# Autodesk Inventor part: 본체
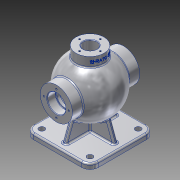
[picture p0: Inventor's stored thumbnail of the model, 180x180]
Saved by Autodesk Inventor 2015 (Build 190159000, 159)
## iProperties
Created: 2025-08
Part Number: 본체
Material: 알루미늄 6061
Document SubType Name: Modeling
Designer: USER
Density: 2.7 g/cm^3
Appearance: 알루미늄 - 평지
Mass: 1478.47 g
Surface Area: 1180.43 cm^2
Volume: 547.582 cm^3
Author: USER
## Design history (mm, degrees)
sketch "스케치1"
  geometry: L1 (-62.5, 62.5)-(62.5, 62.5); L2 (62.5, 62.5)-(62.5, -62.5); L3 (62.5, -62.5)-(-62.5, -62.5); L4 (-62.5, -62.5)-(-62.5, 62.5); L5 (-62.5, 62.5)-(62.5, -62.5); L6 (62.5, 62.5)-(-62.5, -62.5); 1 further point
  constraints: 12 end point, 2 midpoint, 2 parallel, 1 horizontal, 1 perpendicular
  dimensions: "d0" = 125 distance of L2.end L3.end; "d1" = 125 distance of L1.end L2.end
extrude "돌출1" new body sketch "스케치1" distance "d2" = 10; taper "d3" = 0 deg
sketch "스케치2"
  geometry: L1 (62.5, 10)-(62.5, 0) reference; L2 (62.5, 0)-(-62.5, 0) reference; L3 (-62.5, 0)-(-62.5, 10) reference; L4 (-62.5, 10)-(62.5, 10) reference; L5 (0, 139)-(0, 31); A1 r 54 centre (0, 85) between (0, 139) and (0, 31); 3 further points
  constraints: 2 end point, 2 midpoint, 2 point on circle, 1 centre point, 1 coincident, 1 vertical, 1 vertical alignment
  dimensions: "d4" = 108 diameter of A1; "d5" = 85 distance from line of A1.centre L2
revolve "회전1" sketch "스케치2" stored, may be unused: angle "d6" = 90 deg
sketch "스케치5"
  geometry: L1 (-4, -50.5)-(4, -50.5); L2 (4, -50.5)-(4, 50.5); L3 (4, 50.5)-(-4, 50.5); L4 (-4, 50.5)-(-4, -50.5); L5 (-4, -50.5)-(4, 50.5); L6 (4, -50.5)-(-4, 50.5); L7 (-50.5, -4)-(50.5, -4); L8 (50.5, -4)-(50.5, 4); L9 (50.5, 4)-(-50.5, 4); L10 (-50.5, 4)-(-50.5, -4); L11 (-50.5, -4)-(50.5, 4); L12 (50.5, -4)-(-50.5, 4); L13 (-62.5, -62.5)-(-62.5, 62.5) reference; L14 (-62.5, 62.5)-(62.5, 62.5) reference; 1 further point
  constraints: 24 end point, 4 midpoint, 4 parallel, 2 horizontal, 2 perpendicular
  dimensions: "d15" = 12 distance between parallel lines of L10 L13; "d16" = 12 distance between parallel lines of L3 L14; "d17" = 8 distance between parallel lines of L9 L7; "d18" = 8 distance between parallel lines of L4 L2
extrude "돌출4" join sketch "스케치5" distance "d19" = 85; taper "d20" = 0 deg
feature "면 기울기1" dims angle "d21" = 20 deg
node "작업 평면1"
sketch "스케치6"
  geometry: L1 (-25.074, 11.167)-(16.405, 11.167); L2 (16.405, 11.167)-(16.405, 5.163); L3 (16.405, 5.163)-(-25.074, 5.163); L4 (-25.074, 5.163)-(-25.074, 11.167); C1 r 27 at (0, 0); 1 further point
  constraints: 1 centre point, 1 coincident, 2 other
  dimensions: "d23" = 54 diameter of C1
extrude "돌출5" join sketch "스케치6" stored distance "d24" = 85; taper "d25" = 0 deg
node "작업 평면2"
sketch "스케치7"
  geometry: C1 r 31 at (0, 85); 1 further point
  constraints: 1 centre point, 1 vertical alignment
  dimensions: "d27" = 62 diameter of C1; "d28" = 85 distance of C1.centre point (0, 0)
extrude "돌출6" join sketch "스케치7" distance "d29" = 130; taper "d30" = 0 deg
hole "구멍1" diameter "d39" = 30; stored, may be unused: countersink angle "d43" = 90 deg, drill point angle "d45" = 0 deg; dims "d37" = 10, "d38" = 10, "d40" = 6, "d41" = 35, "d42" = 16, "d44" = 8
hole "구멍2" diameter "d48" = 26; stored, may be unused: countersink angle "d52" = 90 deg, drill point angle "d54" = 0 deg; dims "d46" = 10, "d47" = 10, "d49" = 6, "d50" = 35, "d51" = 16, "d53" = 100
sketch "스케치10"
  geometry: L1 (0, 0)-(0, 24); 1 further point
  constraints: 2 end point, 1 vertical
  dimensions: "d55" = 24 distance of L1.start L1.end
hole "구멍3" sketch "스케치10" at (0, 24) diameter "d56" = 3.242; stored, may be unused: countersink angle "d60" = 90 deg, drill point angle "d62" = 118 deg; dims "d57" = 12, "d58" = 35, "d59" = 16, "d61" = 15
sketch "스케치11"
  geometry: L1 (0, 0)-(0, 20)
  constraints: 2 end point, 1 vertical
  dimensions: "d66" = 20 distance of L1.start L1.end
hole "구멍4" sketch "스케치11" at (0, 20) diameter "d67" = 3.242; stored, may be unused: countersink angle "d71" = 90 deg, drill point angle "d73" = 118 deg; dims "d68" = 9, "d69" = 35, "d70" = 16, "d72" = 11
fillet "모깎기1" dims "d78" = 16
hole "구멍5" diameter "d81" = 11; stored, may be unused: countersink angle "d85" = 90 deg, drill point angle "d87" = 0 deg; dims "d79" = 10, "d80" = 10, "d82" = 203.2, "d83" = 35, "d84" = 16, "d86" = 11
hole "구멍6" diameter "d90" = 11; stored, may be unused: countersink angle "d94" = 90 deg, drill point angle "d96" = 0 deg; dims "d88" = 10, "d89" = 10, "d91" = 203.2, "d92" = 35, "d93" = 16, "d95" = 11
hole "구멍7" diameter "d99" = 11; stored, may be unused: countersink angle "d103" = 90 deg, drill point angle "d105" = 0 deg; dims "d97" = 10, "d98" = 10, "d100" = 203.2, "d101" = 35, "d102" = 16, "d104" = 11
hole "구멍8" diameter "d108" = 11; stored, may be unused: countersink angle "d112" = 90 deg, drill point angle "d114" = 0 deg; dims "d106" = 10, "d107" = 10, "d109" = 203.2, "d110" = 35, "d111" = 16, "d113" = 11
sketch "스케치13"
  geometry: L1 (-13, 150)-(13, 150) reference; 3 further points
  constraints: 1 midpoint, 1 vertical alignment, 1 other
  dimensions: "d115" = 9 distance from line of point (0, 141) L1
feature "엠보싱1" sketch "스케치13" dims "d0" = 125, "d1" = 125, "d16" = 12, "d18" = 8, "d116" = 0.5, "d117" = 0
chamfer "모따기1" distance "d118" = 1; stored, may be unused: second distance "d119" = 2, angle "d120" = 45 deg
fillet "모깎기2" dims "d121" = 0.6
fillet "모깎기3" dims "d122" = 3
fillet "모깎기4" dims "d123" = 3
sketch "스케치14"
  geometry: L1 (50, 110.621)-(49.026, 109) reference; L2 (49.026, 109)-(50, 107.379) reference; L3 (50, 107.379)-(65, 107.379) reference; L4 (65, 107.379)-(65, 103.5) reference; L5 (65, 103.5)-(64, 102.5) reference; L6 (64, 102.5)-(49.6, 102.5) reference; L7 (49, 101.9)-(49, 100) reference; L8 (49, 100)-(13, 100) reference; L9 (13, 100)-(13, 149) reference; L10 (13, 149)-(14, 150) reference; L11 (14, 150)-(18.379, 150) reference; L12 (18.379, 150)-(18.379, 139) reference; L13 (18.379, 139)-(20, 138.026) reference; L14 (20, 138.026)-(21.621, 139) reference; L15 (21.621, 139)-(21.621, 150) reference; L16 (21.621, 150)-(27, 150) reference; L17 (27, 150)-(27, 133.466) reference; L18 (45.749, 116)-(65, 116) reference; L19 (65, 116)-(65, 110.621) reference; L20 (65, 110.621)-(50, 110.621) reference; L21 (-49.026, 109)-(-50, 110.621) reference; L22 (-50, 110.621)-(-65, 110.621) reference; L23 (-65, 110.621)-(-65, 116) reference; L24 (-65, 116)-(-45.749, 116) reference; L25 (-27, 133.466)-(-27, 150) reference; L26 (-27, 150)-(-21.621, 150) reference; L27 (-21.621, 150)-(-21.621, 139) reference; L28 (-21.621, 139)-(-20, 138.026) reference; L29 (-20, 138.026)-(-18.379, 139) reference; L30 (-18.379, 139)-(-18.379, 150) reference; L31 (-18.379, 150)-(-14, 150) reference; L32 (-14, 150)-(-13, 149) reference; L33 (-13, 149)-(-13, 100) reference; L34 (-13, 100)-(-49, 100) reference; L35 (-49, 100)-(-49, 101.9) reference; L36 (-49.6, 102.5)-(-64, 102.5) reference; L37 (-64, 102.5)-(-65, 103.5) reference; L38 (-65, 103.5)-(-65, 107.379) reference; L39 (-65, 107.379)-(-50, 107.379) reference; L40 (-50, 107.379)-(-49.026, 109) reference; L41 (-13, 70)-(-13, 50) reference; L42 (-13, 50)-(13, 50) reference; L43 (13, 50)-(13, 70) reference; L44 (13, 70)-(49, 70) reference; L45 (49, 70)-(49, 68.1) reference; L46 (49.6, 67.5)-(64, 67.5) reference; L47 (64, 67.5)-(65, 66.5) reference; L48 (65, 66.5)-(65, 62.621) reference; L49 (65, 62.621)-(50, 62.621) reference; L50 (50, 62.621)-(49.026, 61) reference; L51 (49.026, 61)-(50, 59.379) reference; L52 (50, 59.379)-(65, 59.379) reference; L53 (65, 59.379)-(65, 54) reference; L54 (65, 54)-(45.749, 54) reference; L55 (37.385, 46.034)-(49.782, 11.974) reference; L56 (52.601, 10)-(59.5, 10) reference; L57 (62.5, 7)-(62.5, 0) reference; L58 (62.5, 0)-(-62.5, 0) reference; L59 (-62.5, 0)-(-62.5, 7) reference; L60 (-59.5, 10)-(-52.601, 10) reference; L61 (-49.782, 11.974)-(-37.385, 46.034) reference; L62 (-45.749, 54)-(-65, 54) reference; L63 (-65, 54)-(-65, 59.379) reference; L64 (-65, 59.379)-(-50, 59.379) reference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; A1 r 0.6 centre (49.6, 101.9) between (49.6, 102.5) and (49, 101.9) reference; A2 r 3 centre (30, 133.466) between (27, 133.466) and (28.421, 130.916) reference; A3 r 54 centre (0, 85) between (43.341, 117.211) and (28.421, 130.916) reference; A4 r 3 centre (45.749, 119) between (43.341, 117.211) and (45.749, 116) reference; A5 r 3 centre (-45.749, 119) between (-45.749, 116) and (-43.341, 117.211) reference; A6 r 54 centre (0, 85) between (-28.421, 130.916) and (-43.341, 117.211) reference; A7 r 3 centre (-30, 133.466) between (-28.421, 130.916) and (-27, 133.466) reference; A8 r 0.6 centre (-49.6, 101.9) between (-49, 101.9) and (-49.6, 102.5) reference; A9 r 0.6 centre (49.6, 68.1) between (49, 68.1) and (49.6, 67.5) reference; A10 r 3 centre (45.749, 51) between (45.749, 54) and (43.341, 52.789) reference; A11 r 54 centre (0, 85) between (37.385, 46.034) and (43.341, 52.789) reference; A12 r 3 centre (52.601, 13) between (49.782, 11.974) and (52.601, 10) reference; A13 r 3 centre (59.5, 7) between (62.5, 7) and (59.5, 10) reference; A14 r 3 centre (-59.5, 7) between (-59.5, 10) and (-62.5, 7) reference; A15 r 3 centre (-52.601, 13) between (-52.601, 10) and (-49.782, 11.974) reference; A16 r 54 centre (0, 85) between (-43.341, 52.789) and (-37.385, 46.034) reference; A17 r 3 centre (-45.749, 51) between (-43.341, 52.789) and (-45.749, 54) reference; A18 r 0.6 centre (-49.6, 68.1) between (-49.6, 67.5) and (-49, 68.1) reference; A19 r 44 centre (0, 85) between (-1, 41.011) and (-1, 128.989); A20 r 45.21 centre (0, 85) between (-42.649, 100) and (-42.474, 100.488); A21 r 44 centre (0, 85) between (-42.164, 97.579) and (-43.326, 92.674); 1 further point
  constraints: 6 point on circle, 5 point on line, 3 centre point, 2 end point, 1 coincident, 1 concentric, 1 vertical
  dimensions: "d125" = 44 radius of A19
revolve "회전2" sketch "스케치14" stored, may be unused: angle "d126" = 90 deg
sketch "스케치15"
  geometry: 1 further point
fillet "모깎기5" dims "d127" = 3
node "솔리드1"
mirror "대칭1"
pattern_circular "원형 패턴1" dims angle "d64" = 360 deg
mirror "대칭2"
pattern_circular "원형 패턴2" dims angle "d75" = 360 deg
node "절단 모서리 투영1"
node "절단 모서리 투영2"
other parameters: "d26" = -65, "d124" = 88
